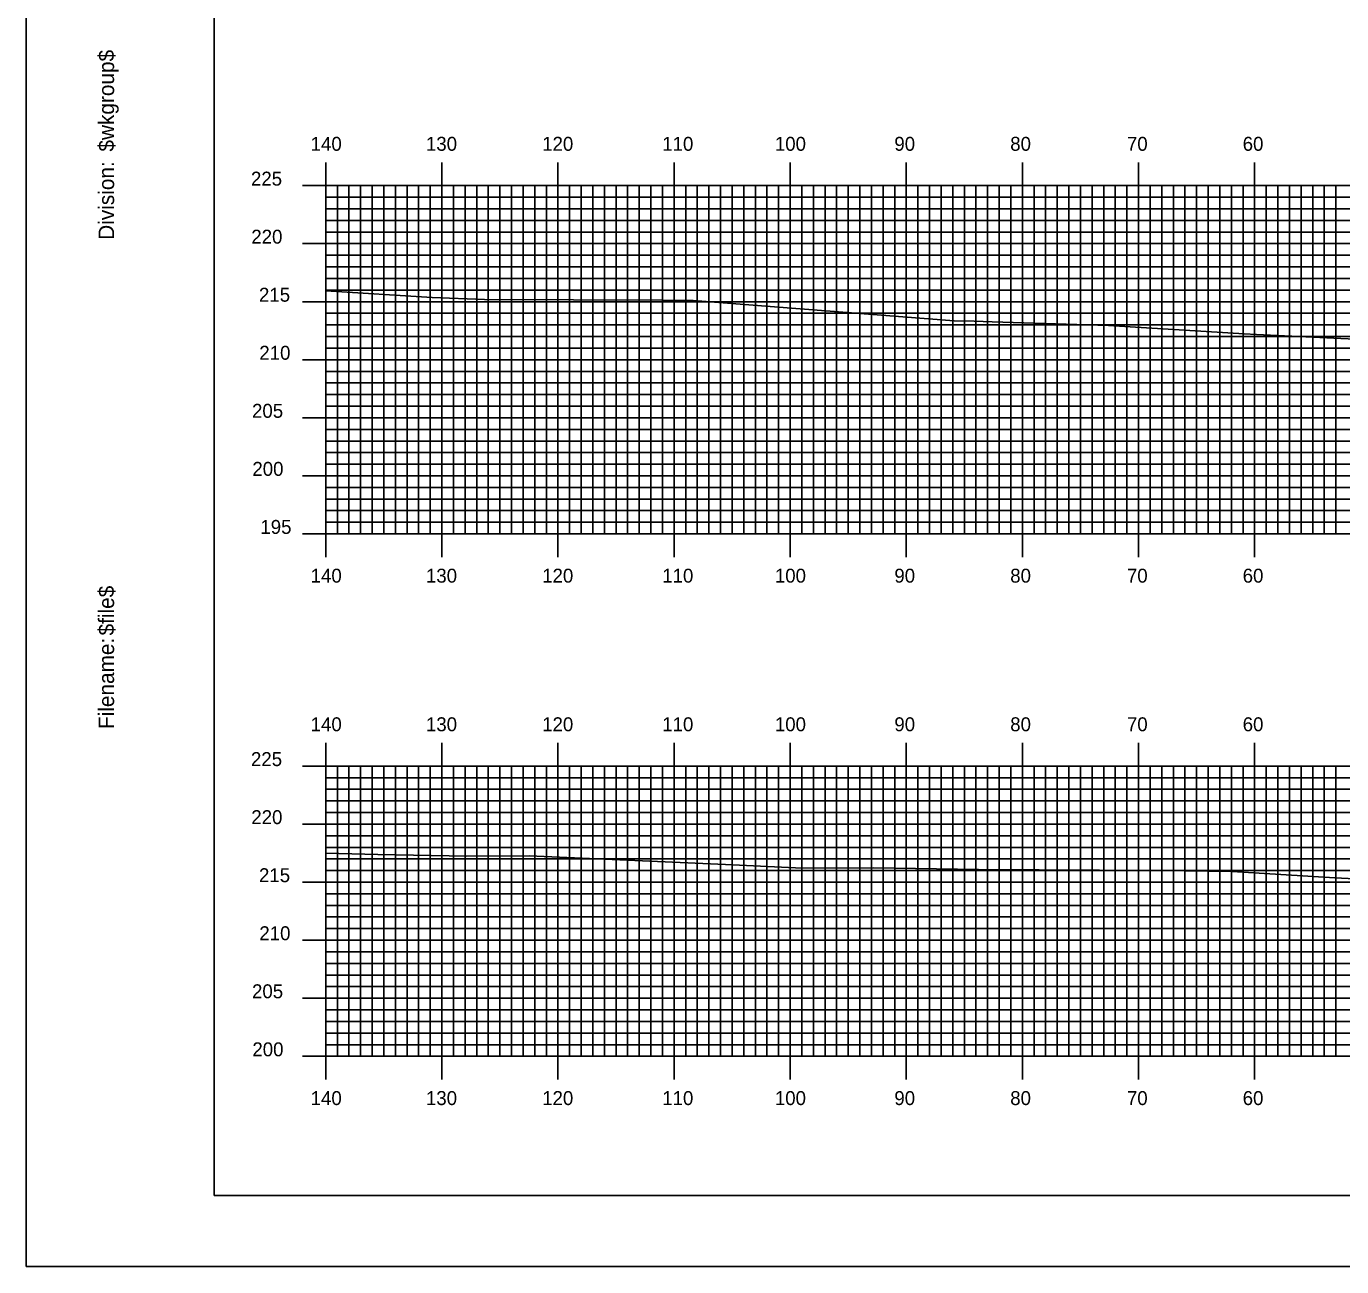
# Model space of a CAD drawing. Extents: x 1805471 to 1805814, y 442591 to 442811.
# Drawn here: x 1805470.9 to 1805584.2, y 442590.5 to 442697.4 of the extents above; entities that cross this region are included whole.
import ezdxf

# ---------------------------------------------------------------- set-up
doc = ezdxf.new("R2010")
doc.units = 0
for name, color, linetype in [('BORDER', 7, 'Continuous'), ('H_V ANNOTATION', 7, 'Continuous'), ('MAJOR', 7, 'Continuous'), ('MINOR', 7, 'Continuous'), ('PLOT BOUNDARY', 7, 'Continuous'), ('S_Roadway_Centerline', 7, 'Continuous')]:
    doc.layers.add(name, color=color, linetype=linetype)

msp = doc.modelspace()

# ---------------------------------------------------------------- linework, layer by layer
at = {"layer": 'BORDER'}
msp.add_lwpolyline([(1805487.11, 442596.67), (1805807.11, 442596.67), (1805807.11, 442806.67), (1805487.11, 442806.67)], close=True, dxfattribs=at)
at = {"layer": 'MAJOR'}
for p, q in [((1805496.71, 442685.67), (1805496.71, 442683.67)), ((1805506.71, 442685.67), (1805506.71, 442683.67)), ((1805516.71, 442685.67), (1805516.71, 442683.67)), ((1805526.71, 442685.67), (1805526.71, 442683.67)), ((1805536.71, 442685.67), (1805536.71, 442683.67)), ((1805546.71, 442685.67), (1805546.71, 442683.67)), ((1805556.71, 442685.67), (1805556.71, 442683.67)), ((1805566.71, 442685.67), (1805566.71, 442683.67)), ((1805576.71, 442685.67), (1805576.71, 442683.67)), ((1805494.7, 442683.67), (1805496.71, 442683.67)), ((1805496.71, 442683.67), (1805776.71, 442683.67)), ((1805496.71, 442653.67), (1805496.71, 442683.67)), ((1805496.71, 442653.67), (1805496.71, 442683.67)), ((1805496.71, 442683.67), (1805776.71, 442683.67)), ((1805506.71, 442653.67), (1805506.71, 442683.67)), ((1805516.71, 442653.67), (1805516.71, 442683.67)), ((1805526.71, 442653.67), (1805526.71, 442683.67)), ((1805536.71, 442653.67), (1805536.71, 442683.67)), ((1805546.71, 442653.67), (1805546.71, 442683.67)), ((1805556.71, 442653.67), (1805556.71, 442683.67)), ((1805566.71, 442653.67), (1805566.71, 442683.67)), ((1805576.71, 442653.67), (1805576.71, 442683.67)), ((1805494.7, 442678.67), (1805496.71, 442678.67)), ((1805496.71, 442678.67), (1805776.71, 442678.67)), ((1805494.7, 442673.67), (1805496.71, 442673.67)), ((1805496.71, 442673.67), (1805776.71, 442673.67)), ((1805494.7, 442668.67), (1805496.71, 442668.67)), ((1805496.71, 442668.67), (1805776.71, 442668.67)), ((1805494.7, 442663.67), (1805496.71, 442663.67)), ((1805496.71, 442663.67), (1805776.71, 442663.67)), ((1805494.7, 442658.67), (1805496.71, 442658.67)), ((1805496.71, 442658.67), (1805776.71, 442658.67)), ((1805494.7, 442653.67), (1805496.71, 442653.67)), ((1805496.71, 442653.67), (1805776.71, 442653.67)), ((1805496.71, 442653.67), (1805776.71, 442653.67)), ((1805496.71, 442651.66), (1805496.71, 442653.67)), ((1805506.71, 442651.66), (1805506.71, 442653.67)), ((1805516.71, 442651.66), (1805516.71, 442653.67)), ((1805526.71, 442651.66), (1805526.71, 442653.67)), ((1805536.71, 442651.66), (1805536.71, 442653.67)), ((1805546.71, 442651.66), (1805546.71, 442653.67)), ((1805556.71, 442651.66), (1805556.71, 442653.67)), ((1805566.71, 442651.66), (1805566.71, 442653.67)), ((1805576.71, 442651.66), (1805576.71, 442653.67)), ((1805496.71, 442635.67), (1805496.71, 442633.67)), ((1805506.71, 442635.67), (1805506.71, 442633.67)), ((1805516.71, 442635.67), (1805516.71, 442633.67)), ((1805526.71, 442635.67), (1805526.71, 442633.67)), ((1805536.71, 442635.67), (1805536.71, 442633.67)), ((1805546.71, 442635.67), (1805546.71, 442633.67)), ((1805556.71, 442635.67), (1805556.71, 442633.67)), ((1805566.71, 442635.67), (1805566.71, 442633.67)), ((1805576.71, 442635.67), (1805576.71, 442633.67)), ((1805494.7, 442633.67), (1805496.71, 442633.67)), ((1805496.71, 442633.67), (1805776.71, 442633.67)), ((1805496.71, 442608.67), (1805496.71, 442633.67)), ((1805496.71, 442608.67), (1805496.71, 442633.67)), ((1805496.71, 442633.67), (1805776.71, 442633.67)), ((1805506.71, 442608.67), (1805506.71, 442633.67)), ((1805516.71, 442608.67), (1805516.71, 442633.67)), ((1805526.71, 442608.67), (1805526.71, 442633.67)), ((1805536.71, 442608.67), (1805536.71, 442633.67)), ((1805546.71, 442608.67), (1805546.71, 442633.67)), ((1805556.71, 442608.67), (1805556.71, 442633.67)), ((1805566.71, 442608.67), (1805566.71, 442633.67)), ((1805576.71, 442608.67), (1805576.71, 442633.67)), ((1805494.7, 442628.67), (1805496.71, 442628.67)), ((1805496.71, 442628.67), (1805776.71, 442628.67)), ((1805494.7, 442623.67), (1805496.71, 442623.67)), ((1805496.71, 442623.67), (1805776.71, 442623.67)), ((1805494.7, 442618.67), (1805496.71, 442618.67)), ((1805496.71, 442618.67), (1805776.71, 442618.67)), ((1805494.7, 442613.67), (1805496.71, 442613.67)), ((1805496.71, 442613.67), (1805776.71, 442613.67)), ((1805494.7, 442608.67), (1805496.71, 442608.67)), ((1805496.71, 442608.67), (1805776.71, 442608.67)), ((1805496.71, 442608.67), (1805776.71, 442608.67)), ((1805496.71, 442606.66), (1805496.71, 442608.67)), ((1805506.71, 442606.66), (1805506.71, 442608.67)), ((1805516.71, 442606.66), (1805516.71, 442608.67)), ((1805526.71, 442606.66), (1805526.71, 442608.67)), ((1805536.71, 442606.66), (1805536.71, 442608.67)), ((1805546.71, 442606.66), (1805546.71, 442608.67)), ((1805556.71, 442606.66), (1805556.71, 442608.67)), ((1805566.71, 442606.66), (1805566.71, 442608.67)), ((1805576.71, 442606.66), (1805576.71, 442608.67))]:
    msp.add_line(p, q, dxfattribs=at)
at = {"layer": 'MINOR'}
for p, q in [((1805497.71, 442653.67), (1805497.71, 442683.67)), ((1805498.71, 442653.67), (1805498.71, 442683.67)), ((1805499.71, 442653.67), (1805499.71, 442683.67)), ((1805500.71, 442653.67), (1805500.71, 442683.67)), ((1805501.71, 442653.67), (1805501.71, 442683.67)), ((1805502.71, 442653.67), (1805502.71, 442683.67)), ((1805503.71, 442653.67), (1805503.71, 442683.67)), ((1805504.71, 442653.67), (1805504.71, 442683.67)), ((1805505.71, 442653.67), (1805505.71, 442683.67)), ((1805507.71, 442653.67), (1805507.71, 442683.67)), ((1805508.71, 442653.67), (1805508.71, 442683.67)), ((1805509.71, 442653.67), (1805509.71, 442683.67)), ((1805510.71, 442653.67), (1805510.71, 442683.67)), ((1805511.71, 442653.67), (1805511.71, 442683.67)), ((1805512.71, 442653.67), (1805512.71, 442683.67)), ((1805513.71, 442653.67), (1805513.71, 442683.67)), ((1805514.71, 442653.67), (1805514.71, 442683.67)), ((1805515.71, 442653.67), (1805515.71, 442683.67)), ((1805517.71, 442653.67), (1805517.71, 442683.67)), ((1805518.71, 442653.67), (1805518.71, 442683.67)), ((1805519.71, 442653.67), (1805519.71, 442683.67)), ((1805520.71, 442653.67), (1805520.71, 442683.67)), ((1805521.71, 442653.67), (1805521.71, 442683.67)), ((1805522.71, 442653.67), (1805522.71, 442683.67)), ((1805523.71, 442653.67), (1805523.71, 442683.67)), ((1805524.71, 442653.67), (1805524.71, 442683.67)), ((1805525.71, 442653.67), (1805525.71, 442683.67)), ((1805527.71, 442653.67), (1805527.71, 442683.67)), ((1805528.71, 442653.67), (1805528.71, 442683.67)), ((1805529.71, 442653.67), (1805529.71, 442683.67)), ((1805530.71, 442653.67), (1805530.71, 442683.67)), ((1805531.71, 442653.67), (1805531.71, 442683.67)), ((1805532.71, 442653.67), (1805532.71, 442683.67)), ((1805533.71, 442653.67), (1805533.71, 442683.67)), ((1805534.71, 442653.67), (1805534.71, 442683.67)), ((1805535.71, 442653.67), (1805535.71, 442683.67)), ((1805537.71, 442653.67), (1805537.71, 442683.67)), ((1805538.71, 442653.67), (1805538.71, 442683.67)), ((1805539.71, 442653.67), (1805539.71, 442683.67)), ((1805540.71, 442653.67), (1805540.71, 442683.67)), ((1805541.71, 442653.67), (1805541.71, 442683.67)), ((1805542.71, 442653.67), (1805542.71, 442683.67)), ((1805543.71, 442653.67), (1805543.71, 442683.67)), ((1805544.71, 442653.67), (1805544.71, 442683.67)), ((1805545.71, 442653.67), (1805545.71, 442683.67)), ((1805547.71, 442653.67), (1805547.71, 442683.67)), ((1805548.71, 442653.67), (1805548.71, 442683.67)), ((1805549.71, 442653.67), (1805549.71, 442683.67)), ((1805550.71, 442653.67), (1805550.71, 442683.67)), ((1805551.71, 442653.67), (1805551.71, 442683.67)), ((1805552.71, 442653.67), (1805552.71, 442683.67)), ((1805553.71, 442653.67), (1805553.71, 442683.67)), ((1805554.71, 442653.67), (1805554.71, 442683.67)), ((1805555.71, 442653.67), (1805555.71, 442683.67)), ((1805557.71, 442653.67), (1805557.71, 442683.67)), ((1805558.71, 442653.67), (1805558.71, 442683.67)), ((1805559.71, 442653.67), (1805559.71, 442683.67)), ((1805560.71, 442653.67), (1805560.71, 442683.67)), ((1805561.71, 442653.67), (1805561.71, 442683.67)), ((1805562.71, 442653.67), (1805562.71, 442683.67)), ((1805563.71, 442653.67), (1805563.71, 442683.67)), ((1805564.71, 442653.67), (1805564.71, 442683.67)), ((1805565.71, 442653.67), (1805565.71, 442683.67)), ((1805567.71, 442653.67), (1805567.71, 442683.67)), ((1805568.71, 442653.67), (1805568.71, 442683.67)), ((1805569.71, 442653.67), (1805569.71, 442683.67)), ((1805570.71, 442653.67), (1805570.71, 442683.67)), ((1805571.71, 442653.67), (1805571.71, 442683.67)), ((1805572.71, 442653.67), (1805572.71, 442683.67)), ((1805573.71, 442653.67), (1805573.71, 442683.67)), ((1805574.71, 442653.67), (1805574.71, 442683.67)), ((1805575.71, 442653.67), (1805575.71, 442683.67)), ((1805577.71, 442653.67), (1805577.71, 442683.67)), ((1805578.71, 442653.67), (1805578.71, 442683.67)), ((1805579.71, 442653.67), (1805579.71, 442683.67)), ((1805580.71, 442653.67), (1805580.71, 442683.67)), ((1805581.71, 442653.67), (1805581.71, 442683.67)), ((1805582.71, 442653.67), (1805582.71, 442683.67)), ((1805583.71, 442653.67), (1805583.71, 442683.67)), ((1805496.71, 442682.67), (1805776.71, 442682.67)), ((1805496.71, 442682.67), (1805498.71, 442682.67)), ((1805496.71, 442681.67), (1805776.71, 442681.67)), ((1805496.71, 442681.67), (1805498.71, 442681.67)), ((1805496.71, 442680.67), (1805776.71, 442680.67)), ((1805496.71, 442680.67), (1805498.71, 442680.67)), ((1805496.71, 442679.67), (1805776.71, 442679.67)), ((1805496.71, 442679.67), (1805498.71, 442679.67)), ((1805496.71, 442677.67), (1805776.71, 442677.67)), ((1805496.71, 442677.67), (1805498.71, 442677.67)), ((1805496.71, 442676.67), (1805776.71, 442676.67)), ((1805496.71, 442676.67), (1805498.71, 442676.67)), ((1805496.71, 442675.67), (1805776.71, 442675.67)), ((1805496.71, 442675.67), (1805498.71, 442675.67)), ((1805496.71, 442674.67), (1805776.71, 442674.67)), ((1805496.71, 442674.67), (1805498.71, 442674.67)), ((1805496.71, 442672.67), (1805776.71, 442672.67)), ((1805496.71, 442672.67), (1805498.71, 442672.67)), ((1805496.71, 442671.67), (1805776.71, 442671.67)), ((1805496.71, 442671.67), (1805498.71, 442671.67)), ((1805496.71, 442670.67), (1805776.71, 442670.67)), ((1805496.71, 442670.67), (1805498.71, 442670.67)), ((1805496.71, 442669.67), (1805776.71, 442669.67)), ((1805496.71, 442669.67), (1805498.71, 442669.67)), ((1805496.71, 442667.67), (1805776.71, 442667.67)), ((1805496.71, 442667.67), (1805498.71, 442667.67)), ((1805496.71, 442666.67), (1805776.71, 442666.67)), ((1805496.71, 442666.67), (1805498.71, 442666.67)), ((1805496.71, 442665.67), (1805776.71, 442665.67)), ((1805496.71, 442665.67), (1805498.71, 442665.67)), ((1805496.71, 442664.67), (1805776.71, 442664.67)), ((1805496.71, 442664.67), (1805498.71, 442664.67)), ((1805496.71, 442662.67), (1805776.71, 442662.67)), ((1805496.71, 442662.67), (1805498.71, 442662.67)), ((1805496.71, 442661.67), (1805776.71, 442661.67)), ((1805496.71, 442661.67), (1805498.71, 442661.67)), ((1805496.71, 442660.67), (1805776.71, 442660.67)), ((1805496.71, 442660.67), (1805498.71, 442660.67)), ((1805496.71, 442659.67), (1805776.71, 442659.67)), ((1805496.71, 442659.67), (1805498.71, 442659.67)), ((1805496.71, 442657.67), (1805776.71, 442657.67)), ((1805496.71, 442657.67), (1805498.71, 442657.67)), ((1805496.71, 442656.67), (1805776.71, 442656.67)), ((1805496.71, 442656.67), (1805498.71, 442656.67)), ((1805496.71, 442655.67), (1805776.71, 442655.67)), ((1805496.71, 442655.67), (1805498.71, 442655.67)), ((1805496.71, 442654.67), (1805776.71, 442654.67)), ((1805496.71, 442654.67), (1805498.71, 442654.67)), ((1805496.71, 442632.67), (1805776.71, 442632.67)), ((1805496.71, 442632.67), (1805498.71, 442632.67)), ((1805497.71, 442608.67), (1805497.71, 442633.67)), ((1805498.71, 442608.67), (1805498.71, 442633.67)), ((1805499.71, 442608.67), (1805499.71, 442633.67)), ((1805500.71, 442608.67), (1805500.71, 442633.67)), ((1805501.71, 442608.67), (1805501.71, 442633.67)), ((1805502.71, 442608.67), (1805502.71, 442633.67)), ((1805503.71, 442608.67), (1805503.71, 442633.67)), ((1805504.71, 442608.67), (1805504.71, 442633.67)), ((1805505.71, 442608.67), (1805505.71, 442633.67)), ((1805507.71, 442608.67), (1805507.71, 442633.67)), ((1805508.71, 442608.67), (1805508.71, 442633.67)), ((1805509.71, 442608.67), (1805509.71, 442633.67)), ((1805510.71, 442608.67), (1805510.71, 442633.67)), ((1805511.71, 442608.67), (1805511.71, 442633.67)), ((1805512.71, 442608.67), (1805512.71, 442633.67)), ((1805513.71, 442608.67), (1805513.71, 442633.67)), ((1805514.71, 442608.67), (1805514.71, 442633.67)), ((1805515.71, 442608.67), (1805515.71, 442633.67)), ((1805517.71, 442608.67), (1805517.71, 442633.67)), ((1805518.71, 442608.67), (1805518.71, 442633.67)), ((1805519.71, 442608.67), (1805519.71, 442633.67)), ((1805520.71, 442608.67), (1805520.71, 442633.67)), ((1805521.71, 442608.67), (1805521.71, 442633.67)), ((1805522.71, 442608.67), (1805522.71, 442633.67)), ((1805523.71, 442608.67), (1805523.71, 442633.67)), ((1805524.71, 442608.67), (1805524.71, 442633.67)), ((1805525.71, 442608.67), (1805525.71, 442633.67)), ((1805527.71, 442608.67), (1805527.71, 442633.67)), ((1805528.71, 442608.67), (1805528.71, 442633.67)), ((1805529.71, 442608.67), (1805529.71, 442633.67)), ((1805530.71, 442608.67), (1805530.71, 442633.67)), ((1805531.71, 442608.67), (1805531.71, 442633.67)), ((1805532.71, 442608.67), (1805532.71, 442633.67)), ((1805533.71, 442608.67), (1805533.71, 442633.67)), ((1805534.71, 442608.67), (1805534.71, 442633.67)), ((1805535.71, 442608.67), (1805535.71, 442633.67)), ((1805537.71, 442608.67), (1805537.71, 442633.67)), ((1805538.71, 442608.67), (1805538.71, 442633.67)), ((1805539.71, 442608.67), (1805539.71, 442633.67)), ((1805540.71, 442608.67), (1805540.71, 442633.67)), ((1805541.71, 442608.67), (1805541.71, 442633.67)), ((1805542.71, 442608.67), (1805542.71, 442633.67)), ((1805543.71, 442608.67), (1805543.71, 442633.67)), ((1805544.71, 442608.67), (1805544.71, 442633.67)), ((1805545.71, 442608.67), (1805545.71, 442633.67)), ((1805547.71, 442608.67), (1805547.71, 442633.67)), ((1805548.71, 442608.67), (1805548.71, 442633.67)), ((1805549.71, 442608.67), (1805549.71, 442633.67)), ((1805550.71, 442608.67), (1805550.71, 442633.67)), ((1805551.71, 442608.67), (1805551.71, 442633.67)), ((1805552.71, 442608.67), (1805552.71, 442633.67)), ((1805553.71, 442608.67), (1805553.71, 442633.67)), ((1805554.71, 442608.67), (1805554.71, 442633.67)), ((1805555.71, 442608.67), (1805555.71, 442633.67)), ((1805557.71, 442608.67), (1805557.71, 442633.67)), ((1805558.71, 442608.67), (1805558.71, 442633.67)), ((1805559.71, 442608.67), (1805559.71, 442633.67)), ((1805560.71, 442608.67), (1805560.71, 442633.67)), ((1805561.71, 442608.67), (1805561.71, 442633.67)), ((1805562.71, 442608.67), (1805562.71, 442633.67)), ((1805563.71, 442608.67), (1805563.71, 442633.67)), ((1805564.71, 442608.67), (1805564.71, 442633.67)), ((1805565.71, 442608.67), (1805565.71, 442633.67)), ((1805567.71, 442608.67), (1805567.71, 442633.67)), ((1805568.71, 442608.67), (1805568.71, 442633.67)), ((1805569.71, 442608.67), (1805569.71, 442633.67)), ((1805570.71, 442608.67), (1805570.71, 442633.67)), ((1805571.71, 442608.67), (1805571.71, 442633.67)), ((1805572.71, 442608.67), (1805572.71, 442633.67)), ((1805573.71, 442608.67), (1805573.71, 442633.67)), ((1805574.71, 442608.67), (1805574.71, 442633.67)), ((1805575.71, 442608.67), (1805575.71, 442633.67)), ((1805577.71, 442608.67), (1805577.71, 442633.67)), ((1805578.71, 442608.67), (1805578.71, 442633.67)), ((1805579.71, 442608.67), (1805579.71, 442633.67)), ((1805580.71, 442608.67), (1805580.71, 442633.67)), ((1805581.71, 442608.67), (1805581.71, 442633.67)), ((1805582.71, 442608.67), (1805582.71, 442633.67)), ((1805583.71, 442608.67), (1805583.71, 442633.67)), ((1805496.71, 442631.67), (1805776.71, 442631.67)), ((1805496.71, 442631.67), (1805498.71, 442631.67)), ((1805496.71, 442630.67), (1805776.71, 442630.67)), ((1805496.71, 442630.67), (1805498.71, 442630.67)), ((1805496.71, 442629.67), (1805776.71, 442629.67)), ((1805496.71, 442629.67), (1805498.71, 442629.67)), ((1805496.71, 442627.67), (1805776.71, 442627.67)), ((1805496.71, 442627.67), (1805498.71, 442627.67)), ((1805496.71, 442626.67), (1805776.71, 442626.67)), ((1805496.71, 442626.67), (1805498.71, 442626.67)), ((1805496.71, 442625.67), (1805776.71, 442625.67)), ((1805496.71, 442625.67), (1805498.71, 442625.67)), ((1805496.71, 442624.67), (1805776.71, 442624.67)), ((1805496.71, 442624.67), (1805498.71, 442624.67)), ((1805496.71, 442622.67), (1805776.71, 442622.67)), ((1805496.71, 442622.67), (1805498.71, 442622.67)), ((1805496.71, 442621.67), (1805776.71, 442621.67)), ((1805496.71, 442621.67), (1805498.71, 442621.67)), ((1805496.71, 442620.67), (1805776.71, 442620.67)), ((1805496.71, 442620.67), (1805498.71, 442620.67)), ((1805496.71, 442619.67), (1805776.71, 442619.67)), ((1805496.71, 442619.67), (1805498.71, 442619.67)), ((1805496.71, 442617.67), (1805776.71, 442617.67)), ((1805496.71, 442617.67), (1805498.71, 442617.67)), ((1805496.71, 442616.67), (1805776.71, 442616.67)), ((1805496.71, 442616.67), (1805498.71, 442616.67)), ((1805496.71, 442615.67), (1805776.71, 442615.67)), ((1805496.71, 442615.67), (1805498.71, 442615.67)), ((1805496.71, 442614.67), (1805776.71, 442614.67)), ((1805496.71, 442614.67), (1805498.71, 442614.67)), ((1805496.71, 442612.67), (1805776.71, 442612.67)), ((1805496.71, 442612.67), (1805498.71, 442612.67)), ((1805496.71, 442611.67), (1805776.71, 442611.67)), ((1805496.71, 442611.67), (1805498.71, 442611.67)), ((1805496.71, 442610.67), (1805776.71, 442610.67)), ((1805496.71, 442610.67), (1805498.71, 442610.67)), ((1805496.71, 442609.67), (1805776.71, 442609.67)), ((1805496.71, 442609.67), (1805498.71, 442609.67))]:
    msp.add_line(p, q, dxfattribs=at)
at = {"layer": 'PLOT BOUNDARY'}
msp.add_lwpolyline([(1805470.92, 442590.55), (1805810.92, 442590.55), (1805810.92, 442810.55), (1805470.92, 442810.55)], close=True, dxfattribs=at)
at = {"layer": 'S_Roadway_Centerline'}
for points in [[(1805496.71, 442674.61), (1805505.87, 442674.02), (1805510.39, 442673.87), (1805525.71, 442673.8), (1805528.34, 442673.78), (1805550.84, 442672.02), (1805552.54, 442671.99), (1805554.11, 442671.93), (1805564.12, 442671.62), (1805575.81, 442670.91), (1805576.88, 442670.84), (1805596.88, 442669.9), (1805598.36, 442669.89), (1805600.11, 442669.9), (1805610.57, 442669.76), (1805632, 442669.48), (1805640.06, 442669.41), (1805645.87, 442669.15), (1805651.44, 442668.26), (1805660.58, 442667.99), (1805669.4, 442668.58), (1805677.43, 442668.19), (1805697.5, 442667.16)], [(1805496.71, 442626.16), (1805501.19, 442626.04), (1805508.87, 442625.91), (1805514.24, 442625.95), (1805531.13, 442625.19), (1805537.78, 442624.88), (1805543.87, 442624.89), (1805552.93, 442624.77), (1805568.56, 442624.67), (1805574.76, 442624.58), (1805583.63, 442624.03), (1805593.85, 442623.53)]]:
    msp.add_lwpolyline(points, dxfattribs=at)

# ---------------------------------------------------------------- texts
at = {"layer": 'BORDER'}
for s, p in [('$wkgroup$', (1805478.48, 442686.6)), ('Division:', (1805478.48, 442679)), ('$file$', (1805478.48, 442644.92)), ('Filename:', (1805478.48, 442636.86))]:
    msp.add_text(s, height=1.339, rotation=90, dxfattribs=at).set_placement(p)
at = {"layer": 'H_V ANNOTATION'}
for s, p in [('140', (1805495.41, 442686.67)), ('130', (1805505.34, 442686.67)), ('120', (1805515.35, 442686.67)), ('110', (1805525.69, 442686.67)), ('100', (1805535.39, 442686.67)), ('90', (1805545.68, 442686.67)), ('80', (1805555.66, 442686.67)), ('70', (1805565.71, 442686.67)), ('60', (1805575.68, 442686.67)), ('225', (1805490.27, 442683.67)), ('220', (1805490.3, 442678.67)), ('215', (1805490.96, 442673.67)), ('210', (1805490.99, 442668.67)), ('205', (1805490.36, 442663.67)), ('200', (1805490.39, 442658.67)), ('195', (1805491.08, 442653.67)), ('140', (1805495.41, 442649.47)), ('130', (1805505.34, 442649.47)), ('120', (1805515.35, 442649.47)), ('110', (1805525.69, 442649.47)), ('100', (1805535.39, 442649.47)), ('90', (1805545.68, 442649.47)), ('80', (1805555.66, 442649.47)), ('70', (1805565.71, 442649.47)), ('60', (1805575.68, 442649.47)), ('140', (1805495.41, 442636.67)), ('130', (1805505.34, 442636.67)), ('120', (1805515.35, 442636.67)), ('110', (1805525.69, 442636.67)), ('100', (1805535.39, 442636.67)), ('90', (1805545.68, 442636.67)), ('80', (1805555.66, 442636.67)), ('70', (1805565.71, 442636.67)), ('60', (1805575.68, 442636.67)), ('225', (1805490.27, 442633.67)), ('220', (1805490.3, 442628.67)), ('215', (1805490.96, 442623.67)), ('210', (1805490.99, 442618.67)), ('205', (1805490.36, 442613.67)), ('200', (1805490.39, 442608.67)), ('140', (1805495.41, 442604.47)), ('130', (1805505.34, 442604.47)), ('120', (1805515.35, 442604.47)), ('110', (1805525.69, 442604.47)), ('100', (1805535.39, 442604.47)), ('90', (1805545.68, 442604.47)), ('80', (1805555.66, 442604.47)), ('70', (1805565.71, 442604.47)), ('60', (1805575.68, 442604.47))]:
    msp.add_text(s, height=1.2, dxfattribs=at).set_placement(p)
at = {"layer": 'MAJOR'}
for p in [(1805496.7, 442653.67), (1805496.7, 442608.67)]:
    msp.add_text('-', height=0.012, dxfattribs=at).set_placement(p)

doc.saveas('drawing.dxf')
